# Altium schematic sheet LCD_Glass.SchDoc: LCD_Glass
size A3; DocumentNumber: MB1144; Revision: B-02; SheetNumber: 5; SheetTotal: 25; PageSetup: Record=PageOptions|CenterHorizontal=True|CenterVertical=True|PrintScale=1.04|XCorrection=1.00|YCorrection=1.00|PrintKind=1|BorderSize=5000000|LeftOffset=0|BottomOffset=0|Orientation=2|PaperLength=1000|PaperWidth=1000|Scale=100|PaperSource=7|PrintQuality=600|MediaType=1|DitherType=10|PaperKind=A3|PrintScaleMode=1; Project: STM32L476G-EVAL
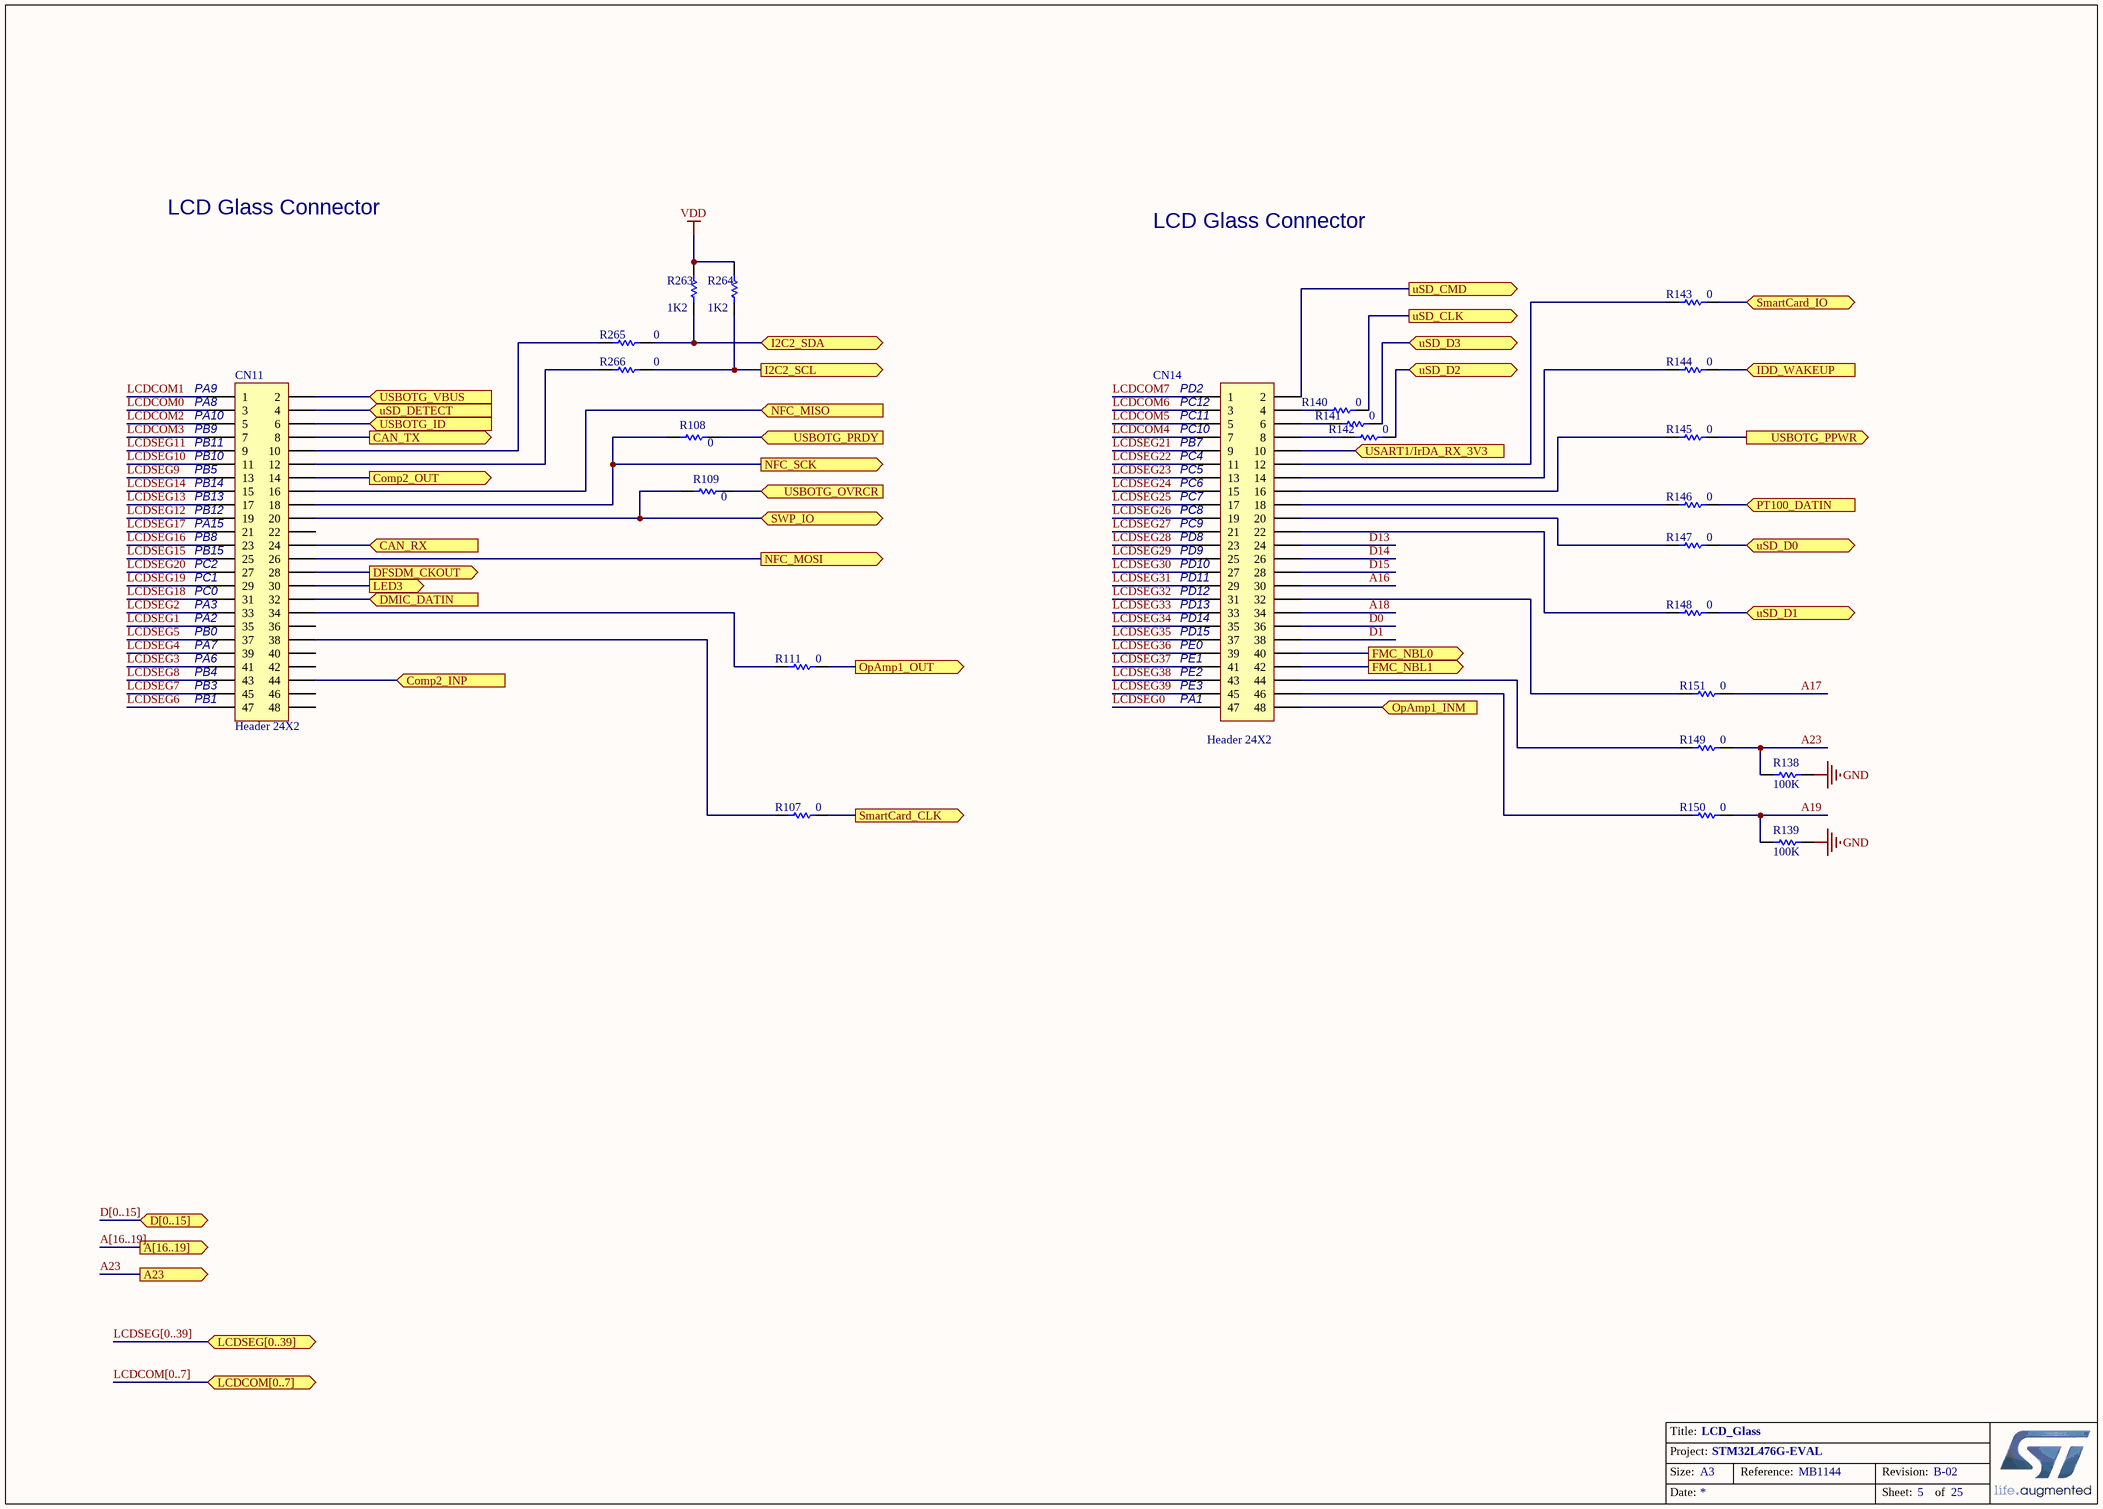
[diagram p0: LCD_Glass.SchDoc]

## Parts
CN11  Header 24X2  [HDR_2X24_2R54]
CN14  Header 24X2  [HDR_2X24_2R54]
R107  0  [0603R]
R108  0  [SB_0603]
R109  0  [SB_0603]
R111  0  [0603R]
R138  100K  [0402R]
R139  100K  [0402R]
R140  0  [0603R]
R141  0  [0603R]
R142  0  [0603R]
R143  0  [0603R]
R144  0  [0603R]
R145  0  [0603R]
R146  0  [0603R]
R147  0  [0603R]
R148  0  [0603R]
R149  0  [0603R]
R150  0  [0603R]
R151  0  [0603R]
R263  1K2  [0402R]
R264  1K2  [0402R]
R265  0  [0603R]
R266  0  [0603R]

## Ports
A23 (out), A[16..19] (out), CAN_RX (in), CAN_TX (out), Comp2_INP (in), Comp2_OUT (out), D[0..15] (bidir), DFSDM_CKOUT (out), DMIC_DATIN (in), FMC_NBL0 (out), FMC_NBL1 (out), I2C2_SCL (out), I2C2_SDA (bidir), IDD_WAKEUP (in), LCDCOM[0..7] (bidir), LCDSEG[0..39] (bidir), LED3 (out), NFC_MISO (in), NFC_MOSI (out), NFC_SCK (out), OpAmp1_INM (in), OpAmp1_OUT (out), PT100_DATIN (in), SmartCard_CLK (out), SmartCard_IO (bidir), SWP_IO (bidir), USART1/IrDA_RX_3V3 (in), USBOTG_ID (in), USBOTG_OVRCR (in), USBOTG_PPWR (out), USBOTG_PRDY (in), USBOTG_VBUS (in), uSD_CLK (out), uSD_CMD (out), uSD_D0 (bidir), uSD_D1 (bidir), uSD_D2 (bidir), uSD_D3 (bidir), uSD_DETECT (in)

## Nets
GND: R138.2 R139.2
VDD: R263.1 R264.1
A16: CN14.30
A17: R151.1
A18: CN14.34
A19: R139.1 R150.1
A23: R138.1 R149.1 ; port A23
CAN_RX: CN11.24 ; port CAN_RX
CAN_TX: CN11.8 ; port CAN_TX
Comp2_INP: CN11.44 ; port Comp2_INP
Comp2_OUT: CN11.14 ; port Comp2_OUT
D0: CN14.36
D1: CN14.38
D13: CN14.24
D14: CN14.26
D15: CN14.28
DFSDM_CKOUT: CN11.28 ; port DFSDM_CKOUT
DMIC_DATIN: CN11.32 ; port DMIC_DATIN
FMC_NBL0: CN14.40 ; port FMC_NBL0
FMC_NBL1: CN14.42 ; port FMC_NBL1
I2C2_SCL: R264.2 R266.1 ; port I2C2_SCL
I2C2_SDA: R263.2 R265.1 ; port I2C2_SDA
IDD_WAKEUP: R144.1 ; port IDD_WAKEUP
LCDCOM0: CN11.3
LCDCOM1: CN11.1
LCDCOM2: CN11.5
LCDCOM3: CN11.7
LCDCOM4: CN14.7
LCDCOM5: CN14.5
LCDCOM6: CN14.3
LCDCOM7: CN14.1
LCDSEG0: CN14.47
LCDSEG1: CN11.35
LCDSEG2: CN11.33
LCDSEG3: CN11.41
LCDSEG4: CN11.39
LCDSEG5: CN11.37
LCDSEG6: CN11.47
LCDSEG7: CN11.45
LCDSEG8: CN11.43
LCDSEG9: CN11.13
LCDSEG10: CN11.11
LCDSEG11: CN11.9
LCDSEG12: CN11.19
LCDSEG13: CN11.17
LCDSEG14: CN11.15
LCDSEG15: CN11.25
LCDSEG16: CN11.23
LCDSEG17: CN11.21
LCDSEG18: CN11.31
LCDSEG19: CN11.29
LCDSEG20: CN11.27
LCDSEG21: CN14.9
LCDSEG22: CN14.11
LCDSEG23: CN14.13
LCDSEG24: CN14.15
LCDSEG25: CN14.17
LCDSEG26: CN14.19
LCDSEG27: CN14.21
LCDSEG28: CN14.23
LCDSEG29: CN14.25
LCDSEG30: CN14.27
LCDSEG31: CN14.29
LCDSEG32: CN14.31
LCDSEG33: CN14.33
LCDSEG34: CN14.35
LCDSEG35: CN14.37
LCDSEG36: CN14.39
LCDSEG37: CN14.41
LCDSEG38: CN14.43
LCDSEG39: CN14.45
LED3: CN11.30 ; port LED3
NFC_MISO: CN11.16 ; port NFC_MISO
NFC_MOSI: CN11.26 ; port NFC_MOSI
NFC_SCK: CN11.18 R108.1 ; port NFC_SCK
OpAmp1_INM: CN14.48 ; port OpAmp1_INM
OpAmp1_OUT: R111.1 ; port OpAmp1_OUT
PT100_DATIN: R146.1 ; port PT100_DATIN
SmartCard_CLK: R107.1 ; port SmartCard_CLK
SmartCard_IO: R143.1 ; port SmartCard_IO
SWP_IO: CN11.20 R109.1 ; port SWP_IO
USART1/IrDA_RX_3V3: CN14.10 ; port USART1/IrDA_RX_3V3
USBOTG_ID: CN11.6 ; port USBOTG_ID
USBOTG_OVRCR: R109.2 ; port USBOTG_OVRCR
USBOTG_PPWR: R145.1 ; port USBOTG_PPWR
USBOTG_PRDY: R108.2 ; port USBOTG_PRDY
USBOTG_VBUS: CN11.2 ; port USBOTG_VBUS
uSD_CLK: R140.1 ; port uSD_CLK
uSD_CMD: CN14.2 ; port uSD_CMD
uSD_D0: R147.1 ; port uSD_D0
uSD_D1: R148.1 ; port uSD_D1
uSD_D2: R142.1 ; port uSD_D2
uSD_D3: R141.1 ; port uSD_D3
uSD_DETECT: CN11.4 ; port uSD_DETECT
NetCN11_10: CN11.10 R265.2
NetCN11_12: CN11.12 R266.2
NetCN11_34: CN11.34 R111.2
NetCN11_38: CN11.38 R107.2
NetCN14_4: CN14.4 R140.2
NetCN14_6: CN14.6 R141.2
NetCN14_8: CN14.8 R142.2
NetCN14_12: CN14.12 R143.2
NetCN14_14: CN14.14 R144.2
NetCN14_16: CN14.16 R145.2
NetCN14_18: CN14.18 R146.2
NetCN14_20: CN14.20 R147.2
NetCN14_22: CN14.22 R148.2
NetCN14_32: CN14.32 R151.2
NetCN14_44: CN14.44 R149.2
NetCN14_46: CN14.46 R150.2

Not connected (* = marked no-connect by the designer): CN11 22 36 40 42 46 48

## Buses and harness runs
bus A[16..19] = port A[16..19]
bus D[0..15] = port D[0..15]
bus LCDCOM[0..7] = port LCDCOM[0..7]
bus LCDSEG[0..39] = port LCDSEG[0..39]

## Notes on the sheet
- LCD Glass Connector
- (near CN11) PA9
- (near CN11) PA8
- (near CN11) PA10
- (near CN11) PB9
- (near CN11) PB11
- (near CN14) PD2
- (near CN14) PC12
- (near CN14) PC11
- (near CN14) PC10
- (near CN14) PB7
- (near CN11) PB10
- (near CN11) PB5
- (near CN11) PB14
- (near CN11) PB13
- (near CN11) PB12
- (near CN14) PC4
- (near CN14) PC5
- (near CN14) PC6
- (near CN14) PC7
- (near CN14) PC
- (near CN14) PC8
- (near CN11) PA15
- (near CN11) PB8
- (near CN11) PB15
- (near CN11) PC2
- (near CN11) PC1
- (near CN14) PD11
- (near CN14) PD10
- (near CN14) PD9
- (near CN14) PD8
- (near CN14) PC9
- (near CN11) PA3
- (near CN11) PA2
- (near CN11) PA7
- (near CN11) PB0
- (near CN11) PC0
- (near CN14) PD12
- (near CN14) PD13
- (near CN14) PD14
- (near CN14) PD15
- (near CN14) PE0
- (near CN11) PA6
- (near CN11) PB4
- (near CN11) PB3
- (near CN11) PB1
- (near CN14) PE1
- (near CN14) PE2
- (near CN14) PE3
- (near CN14) PA1

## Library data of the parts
CN11 CN14 = Header 24X2: Header, 24-Pin, Dual row; Ordered by: Subcon; Comments: LCD Glass connector; ECCN_US/EU: NA; Assembly: with MB979
R107 R111 R138-R151 = res1: Resistor; Value: 1K; Ordered by: Subcon; ECCN_US/EU: NA
R108 R109 R263-R266 = Res1: Resistor; Value: 1K; Ordered by: Subcon; ECCN_US/EU: NA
